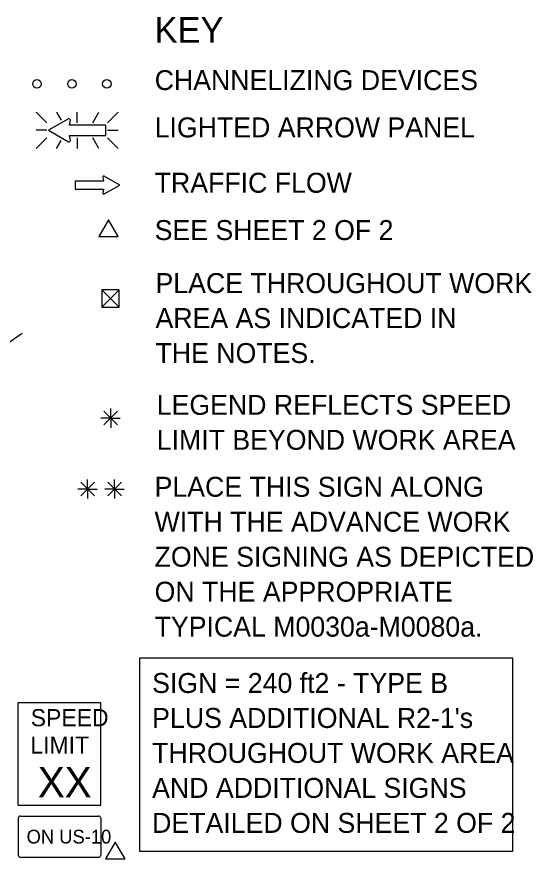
# Model space of a CAD drawing. Extents: x 16303 to 18479, y 5704 to 6974.
# Drawn here: x 17188.8 to 17429.2, y 6525.1 to 6922.2 of the extents above; entities that cross this region are included whole.
import ezdxf

# ---------------------------------------------------------------- set-up
doc = ezdxf.new("R2010")
doc.units = 0
for name, color, linetype in [('MT_SCRATCH_LEVEL_E', 7, 'Continuous'), ('PAVT_EDGE_EX', 7, 'Continuous'), ('TRAFFIC_SIGNS_PR', 7, 'Continuous'), ('TYPICAL_TEXT_DIMEN_EX', 7, 'Continuous'), ('TYPICAL_TEXT_DIMEN_PR', 7, 'Continuous')]:
    doc.layers.add(name, color=color, linetype=linetype)

msp = doc.modelspace()

# ---------------------------------------------------------------- linework, layer by layer
at = {"layer": 'MT_SCRATCH_LEVEL_E'}
for p, q in [((17228.75, 6847.56), (17229.06, 6845.79)), ((17236.67, 6843.94), (17229.44, 6848.05)), ((17229.06, 6845.79), (17215.81, 6845.79)), ((17215.81, 6845.79), (17215.81, 6842.05)), ((17229.44, 6839.79), (17236.67, 6843.94)), ((17215.81, 6842.05), (17229.06, 6842.05)), ((17229.06, 6842.05), (17228.75, 6840.27))]:
    msp.add_line(p, q, dxfattribs=at)
for centre, start, end in [((17229.21, 6847.64), 60.4248, 189.9638), ((17229.21, 6840.2), 170.0362, 299.7731)]:
    msp.add_arc(centre, 0.463, start, end, dxfattribs=at)
at = {"layer": 'PAVT_EDGE_EX'}
msp.add_arc((17357.65, 6525.15), 300, 123.6935, 180, dxfattribs=at)
at = {"layer": 'TRAFFIC_SIGNS_PR'}
for p, q in [((17197.74, 6877.94), (17202.67, 6873.01)), ((17209.5, 6874.12), (17207.3, 6877.94)), ((17216.82, 6873.01), (17216.82, 6877.94)), ((17224.06, 6873.01), (17226.91, 6877.94)), ((17230.97, 6873.01), (17235.91, 6877.95)), ((17202.67, 6869.45), (17197.74, 6869.45)), ((17197.74, 6860.97), (17202.67, 6865.9)), ((17216.82, 6865.9), (17216.82, 6860.96)), ((17226.95, 6860.96), (17224.1, 6865.9)), ((17230.97, 6869.45), (17235.91, 6869.45)), ((17230.97, 6865.9), (17235.91, 6860.96)), ((17207.25, 6860.96), (17209.37, 6864.63)), ((17189.39, 6602.81), (17227.79, 6602.81)), ((17189.39, 6554.81), (17189.39, 6602.81)), ((17227.79, 6554.81), (17227.79, 6602.81)), ((17189.39, 6554.81), (17227.79, 6554.81)), ((17189.39, 6548.81), (17189.39, 6531.61)), ((17190.39, 6549.81), (17226.79, 6549.81)), ((17227.79, 6548.81), (17227.79, 6531.61)), ((17190.39, 6530.61), (17226.79, 6530.61))]:
    msp.add_line(p, q, dxfattribs=at)
for points in [[(17212.75, 6874.73), (17203.46, 6869.45), (17212.75, 6864.13)], [(17213.63, 6864.76), (17213.22, 6867.03), (17230.24, 6867.03), (17230.24, 6871.83), (17213.22, 6871.83), (17213.63, 6874.11)]]:
    msp.add_lwpolyline(points, dxfattribs=at)
for centre in [(17198.08, 6891.14), (17214.38, 6891.14), (17230.68, 6891.14)]:
    msp.add_circle(centre, 2, dxfattribs=at)
for centre, radius, start, end in [((17213.04, 6874.21), 0.598, 350.7308, 118.8916), ((17213.04, 6864.66), 0.597, 241.4833, 9.9593), ((17190.39, 6548.81), 1, 90, 180), ((17226.79, 6548.81), 1, 0, 90), ((17190.39, 6531.61), 1, 180, 270), ((17226.79, 6531.61), 1, 270, 0)]:
    msp.add_arc(centre, radius, start, end, dxfattribs=at)
at = {"layer": 'TYPICAL_TEXT_DIMEN_EX'}
msp.add_lwpolyline([(17245.96, 6623.6), (17419.62, 6623.6), (17419.62, 6533.27), (17245.96, 6533.27)], close=True, dxfattribs=at)
at = {"layer": 'TYPICAL_TEXT_DIMEN_PR'}
for p, q in [((17228.3, 6795.07), (17236.3, 6787.07)), ((17228.3, 6787.07), (17236.3, 6795.07)), ((17232.43, 6735.3), (17232.43, 6739.76)), ((17232.43, 6735.3), (17227.9, 6735.3)), ((17229.24, 6738.49), (17235.62, 6732.11)), ((17235.62, 6738.49), (17229.24, 6732.11)), ((17232.43, 6735.3), (17235.62, 6735.3)), ((17232.43, 6735.3), (17236.91, 6735.3)), ((17232.43, 6735.3), (17232.43, 6730.8)), ((17218.47, 6705.44), (17224.84, 6699.06)), ((17224.84, 6705.44), (17218.47, 6699.06)), ((17221.65, 6702.25), (17221.65, 6706.71)), ((17231.02, 6705.44), (17237.4, 6699.06)), ((17237.4, 6705.44), (17231.02, 6699.06)), ((17234.21, 6702.25), (17234.21, 6706.71)), ((17221.65, 6702.25), (17217.12, 6702.25)), ((17221.65, 6702.25), (17224.84, 6702.25)), ((17221.65, 6702.25), (17226.13, 6702.25)), ((17221.65, 6702.25), (17221.65, 6697.75)), ((17234.21, 6702.25), (17229.68, 6702.25)), ((17234.21, 6702.25), (17237.4, 6702.25)), ((17234.21, 6702.25), (17238.69, 6702.25)), ((17234.21, 6702.25), (17234.21, 6697.75))]:
    msp.add_line(p, q, dxfattribs=at)
for points in [[(17231.39, 6827.76), (17226.86, 6819.93), (17235.91, 6819.93)], [(17228.3, 6795.07), (17228.3, 6787.07), (17236.3, 6787.07), (17236.3, 6795.07)], [(17234.58, 6537.67), (17230.06, 6529.84), (17239.11, 6529.84)]]:
    msp.add_lwpolyline(points, close=True, dxfattribs=at)
msp.add_open_spline([(17346.31, 6772.35), (17346.33, 6772.35), (17346.33, 6772.35), (17346.33, 6772.35)], degree=2, dxfattribs=at)

# ---------------------------------------------------------------- texts
at = {"layer": 'TRAFFIC_SIGNS_PR'}
for s, height, p in [('PLACE THROUGHOUT WORK', 9.3, (17253.31, 6793.57)), ('AREA AS INDICATED IN', 9.3, (17253.31, 6777.27)), ('THE NOTES.', 9.3, (17253.31, 6760.97)), ('PLACE THIS SIGN ALONG', 9.3, (17252.89, 6698.63)), ('WITH THE ADVANCE WORK', 9.3, (17252.89, 6682.33)), ('ZONE SIGNING AS DEPICTED', 9.3, (17252.89, 6666.03)), ('ON THE APPROPRIATE', 9.3, (17252.89, 6649.73)), ('TYPICAL M0030a-M0080a.', 9.3, (17252.89, 6633.43)), ('SPEED', 8, (17195.16, 6591.67)), ('LIMIT', 8, (17195, 6578.87)), ('XX', 14.031, (17198.5, 6558.57)), ('ON US-10', 6.4, (17193.23, 6537.01))]:
    msp.add_text(s, height=height, dxfattribs=at).set_placement(p)
at = {"layer": 'TYPICAL_TEXT_DIMEN_EX'}
for s, height, p in [('KEY', 12, (17252.92, 6910.25)), ('CHANNELIZING DEVICES', 9.3, (17252.92, 6888.2)), ('LIGHTED ARROW PANEL', 9.3, (17252.92, 6866.15)), ('TRAFFIC FLOW', 9.3, (17252.92, 6840.35)), ('SEE SHEET 2 OF 2', 9.3, (17252.92, 6818.3)), ('LEGEND REFLECTS SPEED', 9.3, (17253.88, 6736.83)), ('LIMIT BEYOND WORK AREA', 9.3, (17253.88, 6720.53)), ('SIGN = 240 ft2 - TYPE B', 9.3, (17251.74, 6607.18)), ("PLUS ADDITIONAL R2-1's", 9.3, (17251.74, 6590.88)), ('THROUGHOUT WORK AREA', 9.3, (17251.74, 6574.58)), ('AND ADDITIONAL SIGNS', 9.3, (17251.74, 6558.28)), ('DETAILED ON SHEET 2 OF 2', 9.3, (17251.74, 6541.98))]:
    msp.add_text(s, height=height, dxfattribs=at).set_placement(p)

doc.saveas('drawing.dxf')
